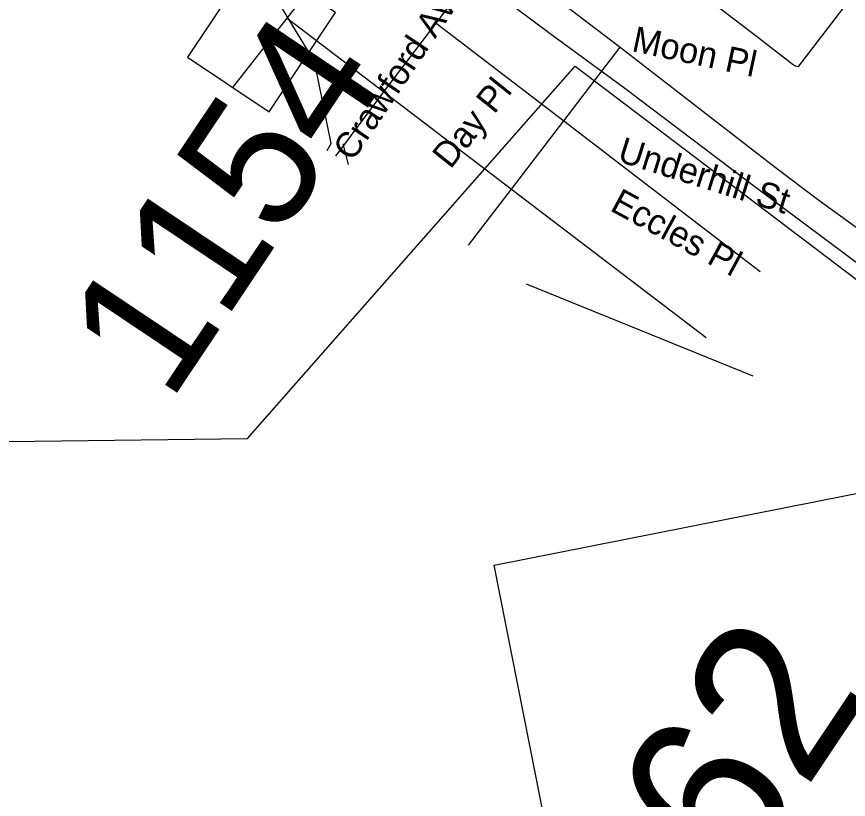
# Model space of a CAD drawing. Extents: x 1716282 to 1717158, y 799307 to 801078.
# Drawn here: x 1716763.01 to 1716807.84, y 800733.65 to 800775.82 of the extents above; entities that cross this region are included whole.
import ezdxf

# ---------------------------------------------------------------- set-up
doc = ezdxf.new("R2010")
doc.units = 0
for name, color, linetype in [('Exist Boundary Political City Limit New', 7, 'Continuous'), ('Exist Hydrographic Misc Water Feature', 7, 'Continuous'), ('Exist Road Non-System Type 51', 7, 'Continuous'), ('Exist Road Non-System Type 51 Label', 7, 'Continuous'), ('Exist Road Secondary Structure NCDOT Private Pedestrian Number Label', 7, 'Continuous'), ('Exist Road Secondary Type 51 Attributed', 7, 'Continuous'), ('Map Preparation Boundary City Limit Buffer Line', 7, 'Continuous'), ('Old_Level_1', 7, 'Continuous'), ('Old_Level_2', 7, 'Continuous')]:
    doc.layers.add(name, color=color, linetype=linetype)

msp = doc.modelspace()

# ---------------------------------------------------------------- linework, layer by layer
at = {"layer": 'Exist Boundary Political City Limit New'}
for points in [[(1716807.449, 800660.825), (1716791.715, 800672.881), (1716792.869, 800679.983), (1716792.149, 800681.666), (1716788.12, 800684.467), (1716789.948, 800687.071), (1716786.94, 800689.425), (1716791.467, 800690.919), (1716795.27, 800692.424), (1716791.49, 800695.9), (1716789.014, 800697.688), (1716781.884, 800702.385), (1716759.136, 800719.878), (1716760.83, 800721.868), (1716732.086, 800743.727), (1716730.156, 800745.69), (1716739.635, 800752.637), (1716775.455, 800753.091), (1716793.108, 800773.151)], [(1716793.108, 800773.151), (1716809.386, 800760.815)]]:
    msp.add_lwpolyline(points, dxfattribs=at)
at = {"layer": 'Exist Hydrographic Misc Water Feature'}
for points in [[(1716779.752, 800768.606), (1716779.969, 800768.981), (1716779.06, 800773.412), (1716773.302, 800782.926), (1716773.169, 800783.886), (1716773.397, 800784.735), (1716773.329, 800786.33), (1716773.47, 800786.879), (1716774.435, 800788.237), (1716774.859, 800788.785), (1716775.418, 800789.507), (1716776.092, 800791.022), (1716776.356, 800794.292), (1716775.692, 800799.57), (1716773.061, 800805.606), (1716767.28, 800813.366), (1716762.4, 800818.012), (1716761.079, 800818.592)], [(1716780.599, 800768.974), (1716780.877, 800767.853)]]:
    msp.add_lwpolyline(points, dxfattribs=at)
at = {"layer": 'Exist Road Non-System Type 51'}
for p, q in [((1716777.595, 800775.749), (1716779.307, 800777.93)), ((1716799.983, 800776.992), (1716802.863, 800774.789)), ((1716774.675, 800772.004), (1716777.595, 800775.749)), ((1716777.595, 800775.749), (1716782.81, 800771.779)), ((1716782.81, 800771.779), (1716785.62, 800775.478)), ((1716785.62, 800775.478), (1716792.509, 800770.21)), ((1716792.509, 800770.21), (1716795.545, 800774.174)), ((1716780.211, 800768.299), (1716782.81, 800771.779)), ((1716782.81, 800771.779), (1716789.679, 800766.523)), ((1716789.679, 800766.523), (1716792.509, 800770.21)), ((1716792.509, 800770.21), (1716803.081, 800762.094)), ((1716787.369, 800763.508), (1716789.679, 800766.523)), ((1716789.679, 800766.523), (1716800.182, 800758.544))]:
    msp.add_line(p, q, dxfattribs=at)
for points in [[(1716785.62, 800775.478), (1716788.583, 800779.351), (1716788.648, 800779.436), (1716795.545, 800774.174)], [(1716802.863, 800774.789), (1716804.884, 800773.225), (1716805.066, 800773.14), (1716805.167, 800773.147), (1716808.732, 800777.803), (1716808.954, 800778.025)], [(1716795.545, 800774.174), (1716803.894, 800767.715), (1716806.257, 800765.944)], [(1716806.257, 800765.944), (1716808.577, 800764.256), (1716813.778, 800761.176)]]:
    msp.add_lwpolyline(points, dxfattribs=at)
at = {"layer": 'Exist Road Secondary Structure NCDOT Private Pedestrian Number Label'}
for p, q in [((1716772.22, 800773.647), (1716776.622, 800770.701)), ((1716802.714, 800756.454), (1716790.499, 800761.413))]:
    msp.add_line(p, q, dxfattribs=at)
msp.add_lwpolyline([(1716776.622, 800770.701), (1716780.204, 800776.053), (1716775.802, 800778.999), (1716772.22, 800773.647)], dxfattribs=at)
at = {"layer": 'Exist Road Secondary Type 51 Attributed'}
msp.add_lwpolyline([(1716809.029, 800761.998), (1716802.935, 800766.551), (1716795.791, 800771.947), (1716791.762, 800774.889), (1716787.196, 800778.327), (1716784.268, 800780.414), (1716782.265, 800781.702), (1716779.752, 800783.191), (1716777.695, 800784.181), (1716773.432, 800786.148)], dxfattribs=at)
at = {"layer": 'Map Preparation Boundary City Limit Buffer Line'}
for points in [[(1716807.449, 800660.825), (1716791.715, 800672.881), (1716792.869, 800679.983), (1716792.149, 800681.666), (1716788.12, 800684.467), (1716789.948, 800687.071), (1716786.94, 800689.425), (1716791.467, 800690.919), (1716795.27, 800692.424), (1716791.49, 800695.9), (1716789.014, 800697.688), (1716781.884, 800702.385), (1716759.136, 800719.878), (1716760.83, 800721.868), (1716732.086, 800743.727), (1716730.156, 800745.69), (1716739.635, 800752.637), (1716775.455, 800753.091), (1716793.108, 800773.151)], [(1716793.108, 800773.151), (1716809.386, 800760.815)]]:
    msp.add_lwpolyline(points, dxfattribs=at)
at = {"layer": 'Old_Level_2'}
msp.add_lwpolyline([(1716793.231, 800723.66), (1716788.752, 800746.267), (1716811.359, 800750.745), (1716815.838, 800728.138)], close=True, dxfattribs=at)

# ---------------------------------------------------------------- texts
at = {"layer": 'Exist Road Non-System Type 51 Label'}
for s, rotation, p in [('Crawford Ave', 56.2051, (1716781.124, 800767.97)), ('Moon Pl', 347.9951, (1716796.114, 800773.97)), ('Day Pl', 51.4236, (1716786.391, 800767.567)), ('Underhill St', 342.5356, (1716795.337, 800768.045)), ('Eccles Pl', 331.4871, (1716794.934, 800765.407))]:
    msp.add_text(s, height=1.3775, rotation=rotation, dxfattribs=at).set_placement(p)
at = {"layer": 'Old_Level_1'}
msp.add_text('1154', height=7.128, rotation=56.2051, dxfattribs=at).set_placement((1716771.258, 800754.959))
at = {"layer": 'Old_Level_2'}
msp.add_text('62', height=8.5641, rotation=56.2051, dxfattribs=at).set_placement((1716801.969, 800728.822))

doc.saveas('drawing.dxf')
